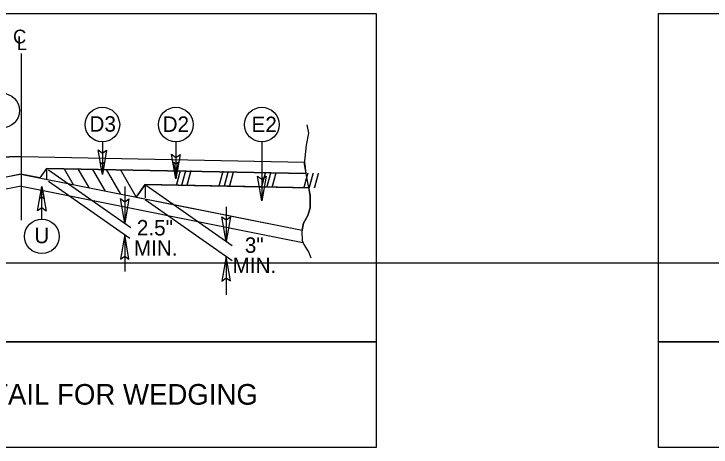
# Model space of a CAD drawing. Extents: x 2320980 to 2456309, y 595047 to 606177.
# Drawn here: x 2455843.3 to 2455910.9, y 597480.7 to 597522.7 of the extents above; entities that cross this region are included whole.
import ezdxf

# ---------------------------------------------------------------- set-up
doc = ezdxf.new("R2010")
doc.units = 0
for name, color, linetype in [('Old_Level_21', 7, 'Continuous'), ('Old_Level_4', 7, 'Continuous'), ('Prop Dimension Text', 7, 'Continuous'), ('Sheet Cutting Line CELL', 7, 'Continuous'), ('Typical Detail Wedge2 CELL', 7, 'Continuous'), ('Typical ID Circle CELL', 7, 'Continuous'), ('Typical Terminator CELL', 7, 'Continuous'), ('Typical Text ID Circle CELL', 7, 'Continuous')]:
    doc.layers.add(name, color=color, linetype=linetype)

msp = doc.modelspace()

# ---------------------------------------------------------------- linework, layer by layer
at = {"layer": 'Old_Level_4'}
for points in [[(2455808.701, 597490.955), (2455878.444, 597490.955), (2455878.444, 597522.716), (2455808.701, 597522.716)], [(2455905.767, 597490.955), (2455975.51, 597490.955), (2455975.51, 597522.716), (2455905.767, 597522.716)], [(2455808.701, 597480.749), (2455878.444, 597480.749), (2455878.444, 597490.955), (2455808.701, 597490.955)], [(2455905.767, 597480.749), (2455975.51, 597480.749), (2455975.51, 597490.955), (2455905.767, 597490.955)]]:
    msp.add_lwpolyline(points, close=True, dxfattribs=at)
at = {"layer": 'Prop Dimension Text'}
msp.add_line((2455844.047, 597502.719), (2455844.047, 597518.873), dxfattribs=at)
at = {"layer": 'Sheet Cutting Line CELL'}
msp.add_line((2456045.507, 597498.574), (2455708.807, 597498.574), dxfattribs=at)
at = {"layer": 'Typical Detail Wedge2 CELL'}
for p, q in [((2455844.046, 597508.891), (2455816.625, 597508.344)), ((2455816.625, 597508.344), (2455844.046, 597508.891)), ((2455844.046, 597508.891), (2455871.469, 597508.344)), ((2455844.049, 597508.891), (2455871.469, 597508.344)), ((2455871.469, 597508.344), (2455871.626, 597507.242)), ((2455846.472, 597507.745), (2455845.836, 597506.842)), ((2455846.472, 597507.745), (2455845.836, 597506.842)), ((2455846.472, 597507.745), (2455871.626, 597507.242)), ((2455871.626, 597507.242), (2455846.472, 597507.745)), ((2455846.488, 597507.735), (2455846.488, 597506.683)), ((2455846.682, 597507.599), (2455854.642, 597502.024)), ((2455848.18, 597507.723), (2455849.075, 597506.19)), ((2455849.556, 597507.652), (2455850.582, 597505.895)), ((2455850.921, 597507.655), (2455852.16, 597505.533)), ((2455852.276, 597507.629), (2455853.656, 597505.261)), ((2455853.646, 597507.601), (2455855.18, 597504.97)), ((2455844.087, 597507.206), (2455816.83, 597501.753)), ((2455844.005, 597507.206), (2455842.256, 597506.842)), ((2455844.005, 597507.206), (2455871.263, 597501.753)), ((2455845.836, 597506.842), (2455844.005, 597507.206)), ((2455844.035, 597506.032), (2455816.821, 597500.589)), ((2455844.057, 597506.032), (2455871.334, 597500.576)), ((2455846.671, 597506.515), (2455854.553, 597500.997)), ((2455854.06, 597505.988), (2455854.06, 597502.432)), ((2455856.042, 597506.178), (2455855.18, 597504.97)), ((2455855.182, 597504.97), (2455856.042, 597506.178)), ((2455856.042, 597506.178), (2455871.892, 597505.861)), ((2455856.042, 597506.178), (2455856.042, 597504.893)), ((2455867.345, 597505.952), (2455856.042, 597506.178)), ((2455856.17, 597506.089), (2455864.47, 597500.276)), ((2455871.892, 597505.861), (2455867.345, 597505.952)), ((2455855.18, 597504.97), (2455858.803, 597504.245)), ((2455856.042, 597504.726), (2455864.456, 597498.832)), ((2455858.803, 597504.245), (2455871.263, 597501.753)), ((2455863.9, 597504.029), (2455863.9, 597500.676)), ((2455854.06, 597501.342), (2455854.06, 597497.752)), ((2455863.9, 597499.223), (2455863.9, 597495.492))]:
    msp.add_line(p, q, dxfattribs=at)
for points in [[(2455871.723, 597511.963), (2455871.869, 597511.159), (2455871.65, 597510.017), (2455871.455, 597508.168), (2455871.723, 597506.709), (2455872.039, 597505.128), (2455872.015, 597503.936), (2455871.819, 597503.182), (2455871.382, 597502.427), (2455871.237, 597501.601), (2455871.26, 597500.774), (2455871.406, 597500.384), (2455871.916, 597499.606), (2455872.086, 597499.07)], [(2455871.263, 597501.753), (2455871.382, 597502.427), (2455871.819, 597503.182), (2455872.015, 597503.936), (2455872.039, 597505.128), (2455871.892, 597505.861)]]:
    msp.add_lwpolyline(points, dxfattribs=at)
at = {"layer": 'Typical ID Circle CELL'}
for p, q in [((2455851.893, 597510.318), (2455851.893, 597507.152)), ((2455859.018, 597510.318), (2455859.018, 597506.733)), ((2455867.345, 597510.317), (2455867.345, 597504.612)), ((2455846.03, 597502.84), (2455846.03, 597506.005))]:
    msp.add_line(p, q, dxfattribs=at)
for centre in [(2455842.187, 597513.35), (2455851.894, 597511.993), (2455859.017, 597511.993), (2455867.345, 597511.993), (2455846.03, 597501.164)]:
    msp.add_circle(centre, 1.676, dxfattribs=at)
at = {"layer": 'Typical Terminator CELL'}
for points in [[(2455852.303, 597509.527), (2455851.893, 597507.152), (2455851.471, 597509.541), (2455851.893, 597509.237)], [(2455859.427, 597509.108), (2455859.018, 597506.733), (2455858.595, 597509.122), (2455859.018, 597508.818)], [(2455852.098, 597508.34), (2455851.893, 597507.152), (2455851.682, 597508.346), (2455851.893, 597508.195)], [(2455859.222, 597508.34), (2455859.018, 597507.152), (2455858.807, 597508.346), (2455859.018, 597508.195)], [(2455867.754, 597506.987), (2455867.345, 597504.612), (2455866.923, 597507), (2455867.345, 597506.697)], [(2455845.621, 597503.63), (2455846.03, 597506.005), (2455846.453, 597503.617), (2455846.03, 597503.92)], [(2455845.826, 597504.818), (2455846.03, 597506.005), (2455846.242, 597504.811), (2455846.03, 597504.963)], [(2455854.469, 597504.808), (2455854.06, 597502.432), (2455853.638, 597504.821), (2455854.06, 597504.517)], [(2455864.309, 597503.051), (2455863.9, 597500.676), (2455863.478, 597503.065), (2455863.9, 597502.761)], [(2455854.469, 597498.967), (2455854.06, 597501.342), (2455853.638, 597498.953), (2455854.06, 597499.257)], [(2455864.309, 597496.848), (2455863.9, 597499.223), (2455863.478, 597496.834), (2455863.9, 597497.138)]]:
    msp.add_lwpolyline(points, close=True, dxfattribs=at)

# ---------------------------------------------------------------- texts
at = {"layer": 'Old_Level_21'}
for s, height, p in [('C', 1.33, (2455843.236, 597519.864)), ('L', 1.33, (2455843.6, 597519.209)), ('W1:  WEDGING     DETAIL FOR WEDGING', 2, (2455814.364, 597484.854))]:
    msp.add_text(s, height=height, dxfattribs=at).set_placement(p)
at = {"layer": 'Typical Detail Wedge2 CELL'}
for height, rotation, p in [(1.3747, 358.85527, (2455858.994, 597506.134)), (1.3746, 358.85361, (2455863.118, 597506.049)), (1.3751, 358.85537, (2455867.236, 597505.929)), (1.3751, 358.85371, (2455871.346, 597505.88))]:
    msp.add_text('/// ', height=height, rotation=rotation, dxfattribs=at).set_placement(p)
for s, p in [('2.5"', (2455855.236, 597501.25)), ('MIN.', (2455854.94, 597499.284)), ('3"', (2455865.698, 597499.567)), ('MIN.', (2455864.513, 597497.6))]:
    msp.add_text(s, height=1.5, dxfattribs=at).set_placement(p)
at = {"layer": 'Typical Text ID Circle CELL'}
for s, p in [('D3', (2455850.642, 597511.309)), ('D2', (2455857.731, 597511.285)), ('E2', (2455866.345, 597511.263)), ('U', (2455845.298, 597500.5))]:
    msp.add_text(s, height=1.5, dxfattribs=at).set_placement(p)

doc.saveas('drawing.dxf')
